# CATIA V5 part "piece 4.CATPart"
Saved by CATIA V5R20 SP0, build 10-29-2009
Part number: piece 4
Bounding box of the stored display mesh (mm): x -19.996 to 19.996, y -519.974 to 19.974, z -10 to 0
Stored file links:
  D:\Dropbox\IAO_2011\MMS_GR1\jdubreuilr\jdubreuilr\jdubreuilr\piece 4.CATPart
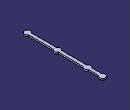
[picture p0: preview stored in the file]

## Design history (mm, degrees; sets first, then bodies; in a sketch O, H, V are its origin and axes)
Set1
  Point1: type OnPlane, Support xy-plane, H 0, V 0, Direction (1, 0, 0)
  Point2: type OnPlane, Support xy-plane, H 0, V -100, Direction (1, 0, 0)
  Point3: type OnPlane, Support xy-plane, H 0, V -300, Direction (1, 0, 0)
  Point4: type OnPlane, Support xy-plane, H 0, V -500, Direction (1, 0, 0)
  Line1: type Normal, RefPoint Point1, RefSkin start face of Pad1, Start 0, End 20
  Line2: type Normal, RefPoint Point2, RefSkin start face of Pad1, Start 0, End 20
  Line3: type Normal, RefPoint Point3, RefSkin start face of Pad1, Start 0, End 20
  Line4: type Normal, RefPoint Point4, RefSkin start face of Pad1, Start 0, End 20
Body1 (main body)
  Sketch1 on xy-plane, origin (0, 0, 0), H (1, 0, 0), V (0, 1, 0)
    line L1 (-10, -17.3205) -> (-10, -82.6795)
    point P2 (-10, -82.6795)
    line L2 (10, -17.3205) -> (10, -82.6795)
    point P3 (10, -17.3205)
    point P4 (10, -82.6795)
    line L3 (10, -117.3205) -> (10, -282.6795)
    point P5 (10, -117.3205)
    point P6 (10, -282.6795)
    line L4 (-10, -117.3205) -> (-10, -282.6795)
    point P7 (-10, -117.3205)
    point P8 (-10, -282.6795)
    line L5 (10, -317.3205) -> (10, -482.6795)
    point P9 (10, -317.3205)
    point P10 (10, -482.6795)
    point P11 (-10, -317.3205)
    arc A1 centre (0, 0) radius 20 from (10, -17.3205) to (-10, -17.3205) ccw
    point P12 (10, -17.3205)
    arc A2 centre (0, -500) radius 20 from (-10, -482.6795) to (10, -482.6795) ccw
    point P13 (0, -500)
    point P15 (10, -482.6795)
    reference projected point E1 (0, -500) from Point4
    arc A3 centre (0, -100) radius 20 from (-10, -82.6795) to (-10, -117.3205) ccw
    point P16 (0, -100)
    point P17 (-10, -117.3205)
    point P18 (-10, -82.6795)
    reference projected point E2 (0, -100) from Point2
    arc A4 centre (0, -100) radius 20 from (10, -117.3205) to (10, -82.6795) ccw
    point P19 (0, -100)
    point P20 (10, -82.6795)
    point P21 (10, -117.3205)
    reference projected point E3 (0, -100) from Point2
    arc A5 centre (0, -300) radius 20 from (-10, -282.6795) to (-10, -317.3205) ccw
    point P22 (0, -300)
    point P23 (-10, -317.3205)
    point P24 (-10, -282.6795)
    reference projected point E4 (0, -300) from Point3
    arc A6 centre (0, -300) radius 20 from (10, -317.3205) to (10, -282.6795) ccw
    point P25 (0, -300)
    point P26 (10, -317.3205)
    point P27 (10, -282.6795)
    reference projected point E5 (0, -300) from Point3
    line L6 (-10, -317.3205) -> (-10, -482.6795)
    radius A1 = 20
    distance L2 V = 10
    distance L1 V = 10
    radius A2 = 20
    radius A3 = 20
    radius A4 = 20
    radius A5 = 20
    radius A6 = 20
    vertical: L1 V, L2 V, L3 V, L4 V, L5 V, L6 V
    coincidence: P5 L2, P7 L1, P9 L2, P11 L1, P12 L2, P12 P3, P13 V, P15 L5, P13 E1, P10 P15, P16 V, P17 L1, P18 L1, P16 E2, P19 V, P20 L2, P21 L2, P19 E3, P18 P2, P17 P7, P20 P4, P21 P5, P22 V, P23 L1, P24 L1, P22 E4, P25 V, P26 L2, A6 P11, P27 L2, P25 E5, P9 P26, P27 P6, P24 P8
  Pad1: profile Sketch1, direction (0, 0, -1), length 10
